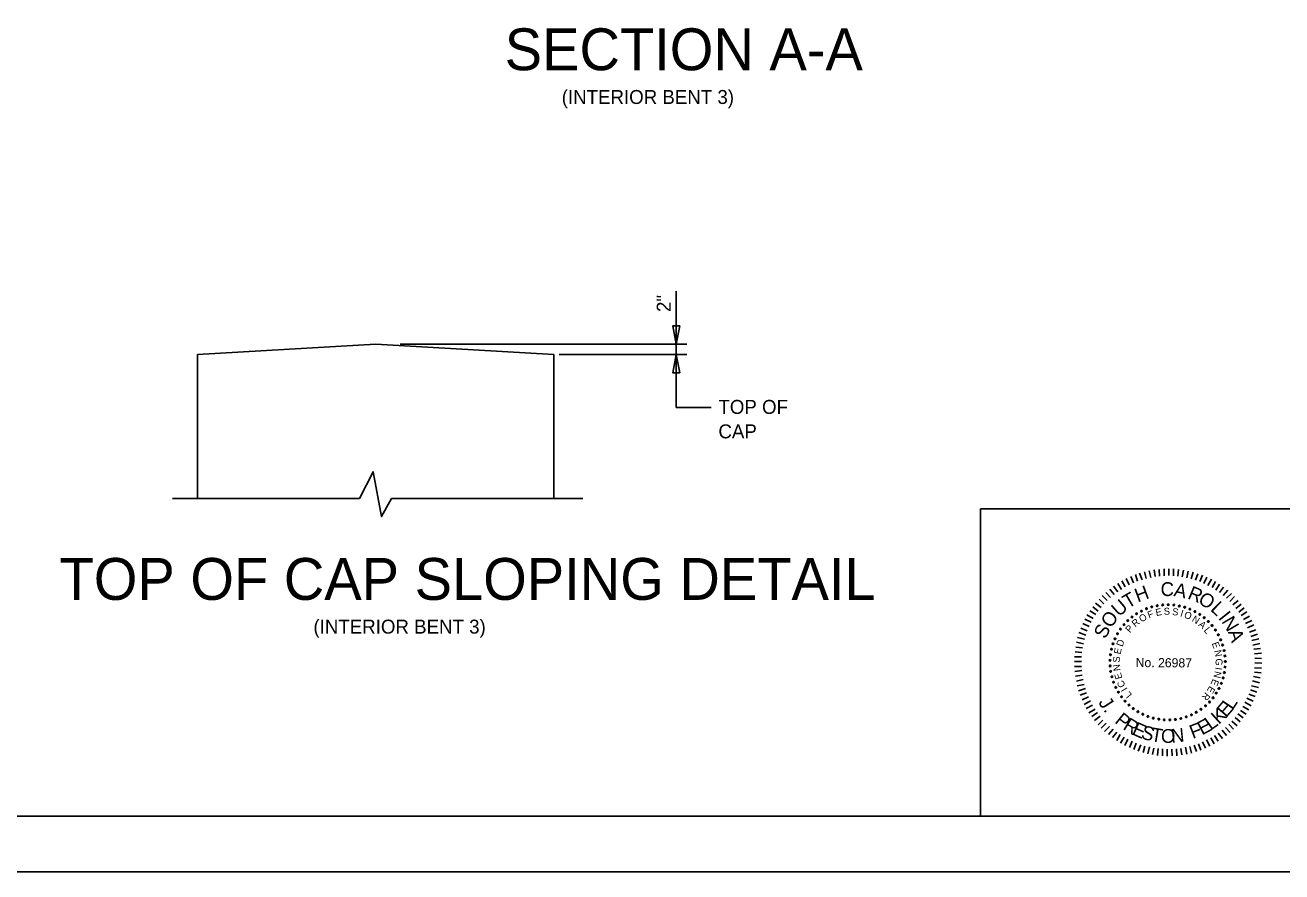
# Model space of a CAD drawing. Extents: x 1970675.2 to 1970711.3, y 796145.2 to 796167.2.
# Drawn here: x 1970689.32 to 1970700.57, y 796145.25 to 796152.83 of the extents above; entities that cross this region are included whole.
import ezdxf

# ---------------------------------------------------------------- set-up
doc = ezdxf.new("R2010")
doc.units = 0
for name, color, linetype in [('BR_AUTO DIMENSION', 7, 'Continuous'), ('BR_BORDER LINES', 7, 'Continuous'), ('BR_CONCRETE', 7, 'Continuous'), ('BR_TEXT', 7, 'Continuous'), ('Default', 7, 'Continuous'), ('Level 31', 7, 'Continuous')]:
    doc.layers.add(name, color=color, linetype=linetype)

msp = doc.modelspace()

# ---------------------------------------------------------------- linework, layer by layer
at = {"layer": 'BR_AUTO DIMENSION'}
for p, q in [((1970695.148, 796150.444), (1970695.148, 796149.403)), ((1970692.679, 796149.971), (1970695.241, 796149.971)), ((1970694.1, 796149.877), (1970695.241, 796149.877)), ((1970695.461, 796149.403), (1970695.148, 796149.403))]:
    msp.add_line(p, q, dxfattribs=at)
for points in [[(1970695.179, 796150.133), (1970695.148, 796149.971), (1970695.117, 796150.133)], [(1970695.179, 796149.714), (1970695.148, 796149.877), (1970695.117, 796149.714)]]:
    msp.add_lwpolyline(points, close=True, dxfattribs=at)
at = {"layer": 'BR_BORDER LINES'}
for p, q in [((1970697.87, 796148.496), (1970703.236, 796148.496)), ((1970697.87, 796145.746), (1970697.87, 796148.496)), ((1970677.07, 796145.746), (1970710.736, 796145.746))]:
    msp.add_line(p, q, dxfattribs=at)
at = {"layer": 'BR_CONCRETE'}
for p, q in [((1970690.865, 796149.877), (1970692.459, 796149.971)), ((1970694.052, 796149.877), (1970692.459, 796149.971)), ((1970690.865, 796149.877), (1970690.865, 796148.588)), ((1970694.052, 796149.877), (1970694.052, 796148.588))]:
    msp.add_line(p, q, dxfattribs=at)
at = {"layer": 'BR_TEXT'}
for p, q in [((1970699.351, 796147.872), (1970699.338, 796147.933)), ((1970699.392, 796147.882), (1970699.378, 796147.941)), ((1970699.432, 796147.889), (1970699.423, 796147.95)), ((1970699.472, 796147.893), (1970699.468, 796147.954)), ((1970699.511, 796147.896), (1970699.512, 796147.96)), ((1970699.553, 796147.898), (1970699.554, 796147.96)), ((1970699.595, 796147.895), (1970699.597, 796147.959)), ((1970699.635, 796147.892), (1970699.64, 796147.953)), ((1970699.674, 796147.887), (1970699.685, 796147.948)), ((1970699.714, 796147.879), (1970699.728, 796147.938)), ((1970699.755, 796147.869), (1970699.771, 796147.93)), ((1970699.13, 796147.774), (1970699.099, 796147.829)), ((1970699.165, 796147.798), (1970699.135, 796147.852)), ((1970699.2, 796147.816), (1970699.174, 796147.872)), ((1970699.237, 796147.833), (1970699.213, 796147.889)), ((1970699.275, 796147.85), (1970699.255, 796147.908)), ((1970699.315, 796147.862), (1970699.293, 796147.92)), ((1970699.792, 796147.858), (1970699.814, 796147.915)), ((1970699.832, 796147.845), (1970699.854, 796147.903)), ((1970699.867, 796147.827), (1970699.895, 796147.883)), ((1970699.903, 796147.81), (1970699.935, 796147.866)), ((1970699.941, 796147.792), (1970699.973, 796147.845)), ((1970699.974, 796147.767), (1970700.008, 796147.821)), ((1970699.003, 796147.676), (1970698.959, 796147.72)), ((1970699.032, 796147.703), (1970698.991, 796147.748)), ((1970699.065, 796147.728), (1970699.025, 796147.778)), ((1970699.099, 796147.753), (1970699.06, 796147.804)), ((1970700.008, 796147.746), (1970700.044, 796147.796)), ((1970700.04, 796147.72), (1970700.081, 796147.769)), ((1970700.071, 796147.695), (1970700.115, 796147.739)), ((1970700.1, 796147.667), (1970700.143, 796147.71)), ((1970698.922, 796147.58), (1970698.873, 796147.62)), ((1970698.948, 796147.614), (1970698.899, 796147.653)), ((1970698.973, 796147.645), (1970698.93, 796147.688)), ((1970700.128, 796147.636), (1970700.175, 796147.677)), ((1970700.155, 796147.604), (1970700.201, 796147.642)), ((1970700.179, 796147.57), (1970700.228, 796147.609)), ((1970698.859, 796147.481), (1970698.802, 796147.508)), ((1970698.876, 796147.515), (1970698.822, 796147.547)), ((1970698.901, 796147.551), (1970698.847, 796147.584)), ((1970700.201, 796147.541), (1970700.253, 796147.573)), ((1970700.223, 796147.504), (1970700.276, 796147.535)), ((1970700.24, 796147.469), (1970700.298, 796147.496)), ((1970698.812, 796147.365), (1970698.75, 796147.388)), ((1970698.824, 796147.405), (1970698.766, 796147.427)), ((1970698.841, 796147.444), (1970698.784, 796147.469)), ((1970700.258, 796147.432), (1970700.315, 796147.457)), ((1970700.275, 796147.393), (1970700.332, 796147.414)), ((1970700.288, 796147.353), (1970700.346, 796147.375)), ((1970698.781, 796147.251), (1970698.721, 796147.259)), ((1970698.792, 796147.287), (1970698.729, 796147.303)), ((1970698.799, 796147.329), (1970698.738, 796147.344)), ((1970700.298, 796147.317), (1970700.359, 796147.331)), ((1970700.307, 796147.275), (1970700.367, 796147.29)), ((1970698.774, 796147.171), (1970698.709, 796147.171)), ((1970698.777, 796147.21), (1970698.715, 796147.217)), ((1970700.315, 796147.239), (1970700.374, 796147.246)), ((1970700.321, 796147.197), (1970700.382, 796147.204)), ((1970700.323, 796147.158), (1970700.383, 796147.157)), ((1970698.772, 796147.129), (1970698.709, 796147.13)), ((1970698.773, 796147.086), (1970698.709, 796147.085)), ((1970698.775, 796147.048), (1970698.714, 796147.041)), ((1970700.32, 796147.035), (1970700.381, 796147.027)), ((1970700.322, 796147.074), (1970700.382, 796147.071)), ((1970700.325, 796147.117), (1970700.386, 796147.116)), ((1970698.779, 796147.007), (1970698.718, 796146.998)), ((1970698.789, 796146.967), (1970698.727, 796146.954)), ((1970698.796, 796146.925), (1970698.735, 796146.911)), ((1970700.295, 796146.913), (1970700.355, 796146.897)), ((1970700.304, 796146.955), (1970700.364, 796146.94)), ((1970700.313, 796146.994), (1970700.372, 796146.984)), ((1970698.808, 796146.888), (1970698.746, 796146.867)), ((1970698.819, 796146.849), (1970698.761, 796146.828)), ((1970698.836, 796146.812), (1970698.778, 796146.785)), ((1970700.253, 796146.801), (1970700.309, 796146.773)), ((1970700.27, 796146.837), (1970700.327, 796146.815)), ((1970700.284, 796146.876), (1970700.342, 796146.854)), ((1970698.853, 796146.776), (1970698.796, 796146.746)), ((1970698.87, 796146.739), (1970698.816, 796146.708)), ((1970698.894, 796146.702), (1970698.839, 796146.671)), ((1970700.194, 796146.691), (1970700.246, 796146.659)), ((1970700.216, 796146.728), (1970700.269, 796146.696)), ((1970700.235, 796146.765), (1970700.292, 796146.734)), ((1970698.915, 796146.673), (1970698.865, 796146.636)), ((1970698.94, 796146.639), (1970698.89, 796146.6)), ((1970698.965, 796146.605), (1970698.921, 796146.564)), ((1970698.994, 796146.579), (1970698.949, 796146.534)), ((1970700.119, 796146.596), (1970700.166, 796146.554)), ((1970700.147, 796146.629), (1970700.193, 796146.589)), ((1970700.171, 796146.662), (1970700.22, 796146.625)), ((1970699.023, 796146.549), (1970698.98, 796146.503)), ((1970699.055, 796146.523), (1970699.014, 796146.476)), ((1970699.088, 796146.497), (1970699.049, 796146.449)), ((1970699.119, 796146.475), (1970699.088, 796146.423)), ((1970699.964, 796146.468), (1970699.997, 796146.416)), ((1970699.997, 796146.489), (1970700.033, 796146.441)), ((1970700.03, 796146.515), (1970700.07, 796146.467)), ((1970700.062, 796146.54), (1970700.104, 796146.494)), ((1970700.09, 796146.57), (1970700.133, 796146.524)), ((1970699.154, 796146.453), (1970699.123, 796146.399)), ((1970699.188, 796146.433), (1970699.161, 796146.377)), ((1970699.225, 796146.415), (1970699.201, 796146.36)), ((1970699.263, 796146.398), (1970699.242, 796146.341)), ((1970699.303, 796146.385), (1970699.28, 796146.327)), ((1970699.339, 796146.373), (1970699.325, 796146.314)), ((1970699.38, 796146.366), (1970699.365, 796146.304)), ((1970699.419, 796146.354), (1970699.409, 796146.296)), ((1970699.661, 796146.352), (1970699.671, 796146.294)), ((1970699.702, 796146.363), (1970699.715, 796146.301)), ((1970699.743, 796146.37), (1970699.758, 796146.31)), ((1970699.78, 796146.381), (1970699.801, 796146.323)), ((1970699.82, 796146.393), (1970699.841, 796146.336)), ((1970699.856, 796146.41), (1970699.883, 796146.354)), ((1970699.892, 796146.427), (1970699.922, 796146.371)), ((1970699.93, 796146.446), (1970699.961, 796146.392)), ((1970699.459, 796146.35), (1970699.454, 796146.288)), ((1970699.498, 796146.347), (1970699.498, 796146.285)), ((1970699.54, 796146.344), (1970699.54, 796146.283)), ((1970699.582, 796146.346), (1970699.584, 796146.284)), ((1970699.623, 796146.348), (1970699.626, 796146.286))]:
    msp.add_line(p, q, dxfattribs=at)
for centre, start, end in [((1970699.309, 796147.581), 27.2191, 207.2191), ((1970699.354, 796147.602), 21.6807, 201.6807), ((1970699.354, 796147.602), 201.6807, 21.6807), ((1970699.401, 796147.618), 16.1422, 196.1422), ((1970699.401, 796147.618), 196.1422, 16.1422), ((1970699.45, 796147.629), 10.6038, 190.6038), ((1970699.45, 796147.629), 190.6038, 10.6038), ((1970699.499, 796147.636), 5.0653, 185.0653), ((1970699.499, 796147.636), 185.0653, 5.0653), ((1970699.549, 796147.638), 359.5268, 179.5268), ((1970699.549, 796147.638), 179.5268, 359.5268), ((1970699.599, 796147.635), 353.9884, 173.9884), ((1970699.599, 796147.635), 173.9884, 353.9884), ((1970699.648, 796147.627), 348.4499, 168.4499), ((1970699.648, 796147.627), 168.4499, 348.4499), ((1970699.696, 796147.615), 342.9114, 162.9114), ((1970699.696, 796147.615), 162.9114, 342.9114), ((1970699.743, 796147.598), 337.373, 157.373), ((1970699.743, 796147.598), 157.373, 337.373), ((1970699.187, 796147.495), 43.8345, 223.8345), ((1970699.187, 796147.495), 223.8345, 43.8345), ((1970699.225, 796147.528), 38.2961, 218.2961), ((1970699.225, 796147.528), 218.2961, 38.2961), ((1970699.265, 796147.557), 32.7576, 212.7576), ((1970699.265, 796147.557), 212.7576, 32.7576), ((1970699.309, 796147.581), 207.2191, 27.2191), ((1970699.788, 796147.576), 151.8345, 331.8345), ((1970699.788, 796147.576), 331.8345, 151.8345), ((1970699.831, 796147.551), 146.2961, 326.2961), ((1970699.831, 796147.551), 326.2961, 146.2961), ((1970699.871, 796147.521), 140.7576, 320.7576), ((1970699.871, 796147.521), 320.7576, 140.7576), ((1970699.907, 796147.488), 135.2191, 315.2191), ((1970699.907, 796147.488), 315.2191, 135.2191), ((1970699.095, 796147.378), 60.4499, 240.4499), ((1970699.095, 796147.378), 240.4499, 60.4499), ((1970699.122, 796147.42), 54.9114, 234.9114), ((1970699.122, 796147.42), 234.9114, 54.9114), ((1970699.153, 796147.459), 49.373, 229.373), ((1970699.153, 796147.459), 229.373, 49.373), ((1970699.941, 796147.451), 129.6807, 309.6807), ((1970699.941, 796147.451), 309.6807, 129.6807), ((1970699.971, 796147.411), 124.1422, 304.1422), ((1970699.971, 796147.411), 304.1422, 124.1422), ((1970699.997, 796147.368), 118.6038, 298.6038), ((1970699.997, 796147.368), 298.6038, 118.6038), ((1970699.055, 796147.287), 71.5268, 251.5268), ((1970699.055, 796147.287), 251.5268, 71.5268), ((1970699.073, 796147.333), 65.9884, 245.9884), ((1970699.073, 796147.333), 245.9884, 65.9884), ((1970700.018, 796147.323), 113.0653, 293.0653), ((1970700.018, 796147.323), 293.0653, 113.0653), ((1970700.036, 796147.277), 107.5268, 287.5268), ((1970700.036, 796147.277), 287.5268, 107.5268), ((1970699.028, 796147.14), 88.1422, 268.1422), ((1970699.032, 796147.19), 82.6038, 262.6038), ((1970699.028, 796147.14), 268.1422, 88.1422), ((1970699.032, 796147.19), 262.6038, 82.6038), ((1970699.041, 796147.239), 77.0653, 257.0653), ((1970699.041, 796147.239), 257.0653, 77.0653), ((1970700.048, 796147.228), 101.9884, 281.9884), ((1970700.048, 796147.228), 281.9884, 101.9884), ((1970700.056, 796147.179), 96.4499, 276.4499), ((1970700.056, 796147.179), 276.4499, 96.4499), ((1970699.029, 796147.09), 93.6807, 273.6807), ((1970699.034, 796147.041), 99.2191, 279.2191), ((1970699.029, 796147.09), 273.6807, 93.6807), ((1970699.034, 796147.041), 279.2191, 99.2191), ((1970700.051, 796147.03), 79.8345, 259.8345), ((1970700.057, 796147.08), 85.373, 265.373), ((1970700.051, 796147.03), 259.8345, 79.8345), ((1970700.059, 796147.129), 90.9114, 270.9114), ((1970700.057, 796147.08), 265.373, 85.373), ((1970700.059, 796147.129), 270.9114, 90.9114), ((1970699.045, 796146.992), 104.7576, 284.7576), ((1970699.045, 796146.992), 284.7576, 104.7576), ((1970699.059, 796146.944), 110.2961, 290.2961), ((1970699.059, 796146.944), 290.2961, 110.2961), ((1970700.024, 796146.934), 68.7576, 248.7576), ((1970700.024, 796146.934), 248.7576, 68.7576), ((1970700.04, 796146.982), 74.2961, 254.2961), ((1970700.04, 796146.982), 254.2961, 74.2961), ((1970699.079, 796146.898), 115.8345, 295.8345), ((1970699.079, 796146.898), 295.8345, 115.8345), ((1970699.103, 796146.855), 121.373, 301.373), ((1970699.103, 796146.855), 301.373, 121.373), ((1970699.131, 796146.813), 126.9114, 306.9114), ((1970699.131, 796146.813), 306.9114, 126.9114), ((1970699.95, 796146.805), 52.1422, 232.1422), ((1970699.95, 796146.805), 232.1422, 52.1422), ((1970699.979, 796146.846), 57.6807, 237.6807), ((1970699.979, 796146.846), 237.6807, 57.6807), ((1970700.003, 796146.889), 63.2191, 243.2191), ((1970700.003, 796146.889), 243.2191, 63.2191), ((1970699.162, 796146.775), 132.4499, 312.4499), ((1970699.162, 796146.775), 312.4499, 132.4499), ((1970699.198, 796146.74), 137.9884, 317.9884), ((1970699.198, 796146.74), 317.9884, 137.9884), ((1970699.236, 796146.708), 143.5268, 323.5268), ((1970699.236, 796146.708), 323.5268, 143.5268), ((1970699.842, 796146.702), 35.5268, 215.5268), ((1970699.842, 796146.702), 215.5268, 35.5268), ((1970699.882, 796146.733), 41.0653, 221.0653), ((1970699.882, 796146.733), 221.0653, 41.0653), ((1970699.918, 796146.767), 46.6038, 226.6038), ((1970699.918, 796146.767), 226.6038, 46.6038), ((1970699.278, 796146.68), 149.0653, 329.0653), ((1970699.278, 796146.68), 329.0653, 149.0653), ((1970699.321, 796146.657), 154.6038, 334.6038), ((1970699.321, 796146.657), 334.6038, 154.6038), ((1970699.367, 796146.638), 160.1422, 340.1422), ((1970699.367, 796146.638), 340.1422, 160.1422), ((1970699.415, 796146.623), 345.6807, 165.6807), ((1970699.415, 796146.623), 165.6807, 345.6807), ((1970699.464, 796146.613), 351.2191, 171.2191), ((1970699.464, 796146.613), 171.2191, 351.2191), ((1970699.513, 796146.607), 356.7576, 176.7576), ((1970699.513, 796146.607), 176.7576, 356.7576), ((1970699.563, 796146.607), 2.2961, 182.2961), ((1970699.563, 796146.607), 182.2961, 2.2961), ((1970699.613, 796146.611), 7.8345, 187.8345), ((1970699.613, 796146.611), 187.8345, 7.8345), ((1970699.662, 796146.62), 13.373, 193.373), ((1970699.662, 796146.62), 193.373, 13.373), ((1970699.71, 796146.634), 18.9114, 198.9114), ((1970699.71, 796146.634), 198.9114, 18.9114), ((1970699.756, 796146.652), 24.4499, 204.4499), ((1970699.756, 796146.652), 204.4499, 24.4499), ((1970699.8, 796146.675), 29.9884, 209.9884), ((1970699.8, 796146.675), 209.9884, 29.9884)]:
    msp.add_arc(centre, 0.00701, start, end, dxfattribs=at)
at = {"layer": 'Default'}
for p, q in [((1970690.642, 796148.588), (1970692.313, 796148.588)), ((1970692.6, 796148.588), (1970694.312, 796148.588))]:
    msp.add_line(p, q, dxfattribs=at)
msp.add_lwpolyline([(1970692.6, 796148.588), (1970692.512, 796148.426), (1970692.436, 796148.828), (1970692.313, 796148.588)], dxfattribs=at)
at = {"layer": 'Level 31'}
msp.add_lwpolyline([(1970675.236, 796167.246), (1970675.236, 796145.246), (1970711.236, 796145.246), (1970711.236, 796167.246)], dxfattribs=at)

# ---------------------------------------------------------------- texts
at = {"layer": 'BR_AUTO DIMENSION'}
msp.add_text('2"', height=0.125, rotation=90, dxfattribs=at).set_placement((1970695.098, 796150.258))
for s, p in [('TOP OF', (1970695.525, 796149.346)), ('CAP', (1970695.525, 796149.127))]:
    msp.add_text(s, height=0.125, dxfattribs=at).set_placement(p)
at = {"layer": 'BR_TEXT'}
for s, p in [('SECTION A-A', (1970693.613, 796152.422)), ('TOP OF CAP SLOPING DETAIL', (1970689.631, 796147.681))]:
    msp.add_text(s, height=0.375, dxfattribs=at).set_placement(p)
for s, height, rotation, p in [('(INTERIOR BENT 3)', 0.125, 360, (1970694.123, 796152.12)), ('C', 0.124, 359.5482, (1970699.48, 796147.716)), ('A', 0.124, 348.1981, (1970699.592, 796147.716)), ('T', 0.124, 30.4992, (1970699.188, 796147.6)), ('H', 0.124, 20.3637, (1970699.276, 796147.657)), ('R', 0.124, 337.4344, (1970699.715, 796147.696)), ('O', 0.124, 326.5869, (1970699.807, 796147.66)), ('U', 0.124, 40.8022, (1970699.107, 796147.525)), ('F', 0.0622, 20.6127, (1970699.377, 796147.514)), ('E', 0.0622, 11.4103, (1970699.442, 796147.536)), ('S', 0.0622, 2.208, (1970699.51, 796147.547)), ('S', 0.0622, 352.6608, (1970699.581, 796147.547)), ('I', 0.0622, 343.1136, (1970699.652, 796147.535)), ('L', 0.124, 315.9488, (1970699.92, 796147.592)), ('(INTERIOR BENT 3)', 0.125, 360, (1970691.902, 796147.379)), ('O', 0.124, 52.0267, (1970699.032, 796147.421)), ('R', 0.0622, 40.3949, (1970699.254, 796147.434)), ('O', 0.0622, 30.8477, (1970699.31, 796147.478)), ('O', 0.0622, 338.4392, (1970699.685, 796147.525)), ('N', 0.0622, 328.2042, (1970699.755, 796147.493)), ('A', 0.0622, 318.657, (1970699.814, 796147.453)), ('I', 0.124, 308.6613, (1970699.991, 796147.518)), ('N', 0.124, 300.7037, (1970700.022, 796147.488)), ('S', 0.124, 63.2511, (1970698.987, 796147.325)), ('P', 0.0622, 49.9421, (1970699.206, 796147.382)), ('L', 0.0622, 309.4546, (1970699.863, 796147.406)), ('A', 0.124, 289.4792, (1970700.081, 796147.395)), ('E', 0.0622, 78.2388, (1970699.122, 796147.19)), ('D', 0.0622, 69.0364, (1970699.139, 796147.257)), ('E', 0.0622, 291.049, (1970699.937, 796147.291)), ('S', 0.0622, 87.786, (1970699.116, 796147.119)), ('No. 26987', 0.0817, 359.5268, (1970699.257, 796147.08)), ('N', 0.0622, 281.8466, (1970699.96, 796147.226)), ('G', 0.0622, 272.2995, (1970699.971, 796147.155)), ('N', 0.0622, 97.3332, (1970699.122, 796147.048)), ('E', 0.0622, 106.5355, (1970699.14, 796146.981)), ('N', 0.0622, 257.7339, (1970699.966, 796147.047)), ('I', 0.0622, 262.4084, (1970699.971, 796147.081)), ('C', 0.0622, 116.4266, (1970699.169, 796146.914)), ('E', 0.0622, 248.1867, (1970699.948, 796146.978)), ('J', 0.124, 302.9559, (1970698.92, 796146.763)), ('I', 0.0622, 121.1011, (1970699.187, 796146.884)), ('L', 0.0622, 129.9595, (1970699.228, 796146.832)), ('R', 0.0622, 229.782, (1970699.883, 796146.858)), ('E', 0.0622, 238.9844, (1970699.92, 796146.915)), ('.', 0.124, 309.3974, (1970698.964, 796146.695)), ('K', 0.124, 42.3031, (1970700.001, 796146.561)), ('E', 0.124, 49.3639, (1970700.066, 796146.621)), ('L', 0.124, 56.4247, (1970700.124, 796146.689)), ('P', 0.124, 321.1035, (1970699.063, 796146.586)), ('R', 0.124, 328.5359, (1970699.136, 796146.528)), ('E', 0.124, 335.9684, (1970699.216, 796146.48)), ('F', 0.124, 21.1206, (1970699.768, 796146.435)), ('E', 0.124, 28.1814, (1970699.851, 796146.467)), ('L', 0.124, 35.2422, (1970699.929, 796146.51)), ('S', 0.124, 343.0292, (1970699.297, 796146.444)), ('T', 0.124, 350.4617, (1970699.387, 796146.418)), ('O', 0.124, 358.1419, (1970699.482, 796146.403)), ('N', 0.124, 5.8221, (1970699.579, 796146.401))]:
    msp.add_text(s, height=height, rotation=rotation, dxfattribs=at).set_placement(p)

doc.saveas('drawing.dxf')
